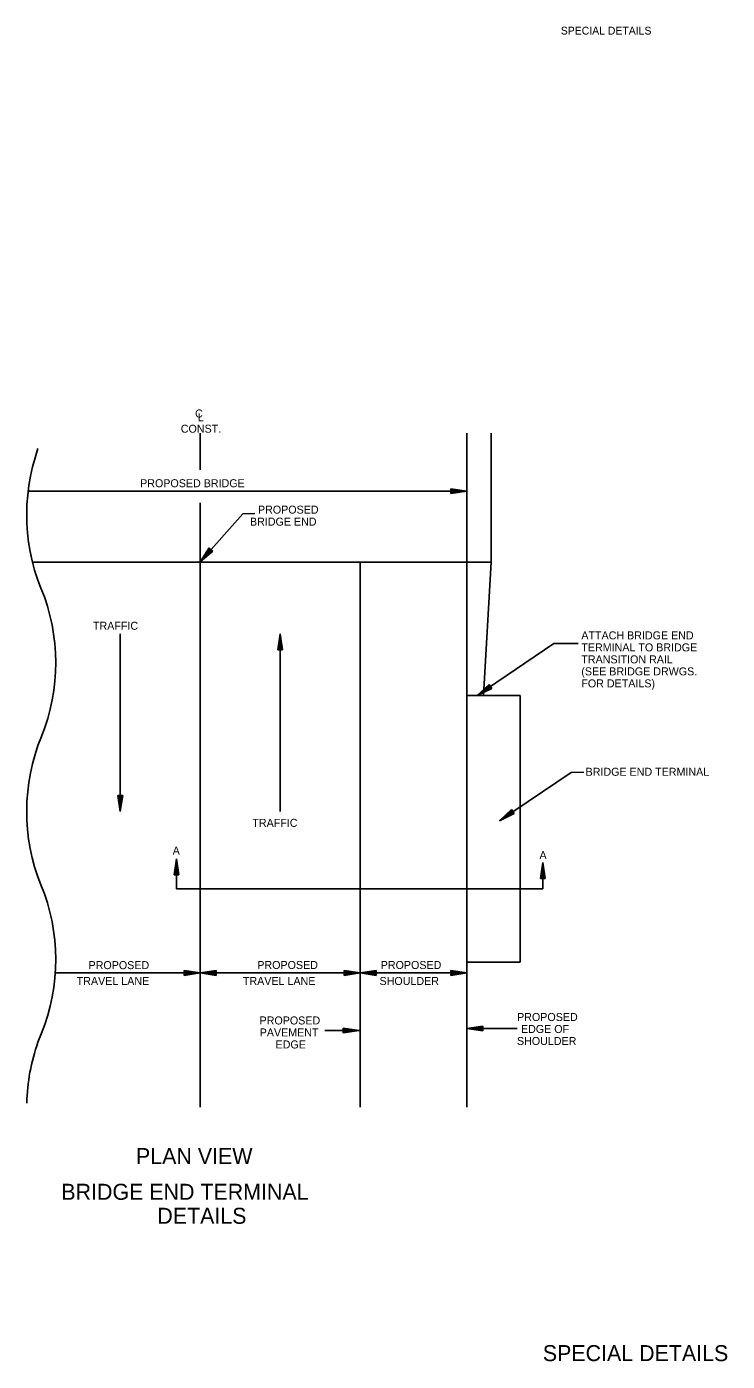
# Model space of a CAD drawing. Extents: x 1929624 to 1935547, y 596315 to 605721.
# Drawn here: x 1933758 to 1934284, y 604034 to 605035 of the extents above; entities that cross this region are included whole.
import ezdxf

# ---------------------------------------------------------------- set-up
doc = ezdxf.new("R2010")
doc.units = 0
for name, color, linetype in [('Default', 7, 'Continuous'), ('R_Annotation', 7, 'Continuous'), ('R_Border', 7, 'Continuous')]:
    doc.layers.add(name, color=color, linetype=linetype)

msp = doc.modelspace()

# ---------------------------------------------------------------- linework, layer by layer
at = {"layer": 'Default'}
for p, q in [((1933888.7, 604730.6), (1933888.7, 604703)), ((1934088.7, 604730.6), (1934088.7, 604633.8)), ((1934107, 604730.6), (1934107, 604633.8)), ((1933759.5, 604687), (1934088.7, 604687)), ((1934076.7, 604688.8), (1934088.7, 604687)), ((1934076.7, 604688.8), (1934076.7, 604685.2)), ((1934076.7, 604688.5), (1934086.7, 604687)), ((1934076.7, 604688.2), (1934084.6, 604687)), ((1934076.7, 604687.9), (1934082.6, 604687)), ((1934076.7, 604687.6), (1934080.6, 604687)), ((1934076.7, 604687.3), (1934078.6, 604687)), ((1934076.7, 604685.2), (1934088.7, 604687)), ((1934076.7, 604686.4), (1934080.6, 604687)), ((1934076.7, 604685.8), (1934084.6, 604687)), ((1934076.7, 604685.5), (1934086.7, 604687)), ((1934076.7, 604686.1), (1934082.6, 604687)), ((1934076.7, 604686.7), (1934078.6, 604687)), ((1933888.7, 604678.4), (1933888.7, 604225)), ((1933888.8, 604634.4), (1933920.7, 604670.1)), ((1933920.7, 604670.1), (1933929.7, 604670.2)), ((1933895.4, 604644.5), (1933888.8, 604634.4)), ((1933898.1, 604642.1), (1933888.8, 604634.4)), ((1933895.7, 604644.3), (1933890.1, 604635.9)), ((1933897.9, 604642.3), (1933890.1, 604635.9)), ((1933895.9, 604644.1), (1933891.5, 604637.4)), ((1933897.7, 604642.5), (1933891.5, 604637.4)), ((1933896.1, 604643.9), (1933892.8, 604638.9)), ((1933897.5, 604642.7), (1933892.8, 604638.9)), ((1933896.3, 604643.7), (1933894.2, 604640.4)), ((1933897.2, 604642.9), (1933894.2, 604640.4)), ((1933898.1, 604642.1), (1933895.4, 604644.5)), ((1933896.6, 604643.5), (1933895.5, 604641.9)), ((1933897, 604643.1), (1933895.5, 604641.9)), ((1933762.8, 604633.8), (1934107, 604633.8)), ((1934008.7, 604633.8), (1934008.7, 604225)), ((1934088.7, 604633.8), (1934088.7, 604533.8)), ((1934101.2, 604533.8), (1934107, 604633.8)), ((1933828.7, 604580), (1933828.7, 604446.9)), ((1933946.9, 604568), (1933948.7, 604580)), ((1933947.2, 604568), (1933948.7, 604578)), ((1933947.5, 604568), (1933948.7, 604575.9)), ((1933948.7, 604580), (1933948.7, 604446.9)), ((1933950.5, 604568), (1933948.7, 604580)), ((1933950.2, 604568), (1933948.7, 604578)), ((1933949.9, 604568), (1933948.7, 604575.9)), ((1933946.9, 604568), (1933950.5, 604568)), ((1933947.8, 604568), (1933948.7, 604573.9)), ((1933948.1, 604568), (1933948.7, 604571.9)), ((1933948.4, 604568), (1933948.7, 604569.9)), ((1933949.6, 604568), (1933948.7, 604573.9)), ((1933949.3, 604568), (1933948.7, 604571.9)), ((1933949, 604568), (1933948.7, 604569.9)), ((1934096.5, 604533.9), (1934154, 604572.9)), ((1934154, 604572.9), (1934172.1, 604572.9)), ((1934088.7, 604536), (1934088.7, 604225)), ((1934105.4, 604542.1), (1934096.5, 604533.9)), ((1934107.4, 604539.1), (1934096.5, 604533.9)), ((1934105.6, 604541.9), (1934098.2, 604535)), ((1934107.3, 604539.4), (1934098.2, 604535)), ((1934105.8, 604541.6), (1934099.9, 604536.2)), ((1934107.1, 604539.7), (1934099.9, 604536.2)), ((1934105.9, 604541.4), (1934101.5, 604537.3)), ((1934106.9, 604539.9), (1934101.5, 604537.3)), ((1934106.1, 604541.1), (1934103.2, 604538.5)), ((1934106.8, 604540.2), (1934103.2, 604538.5)), ((1934106.3, 604540.9), (1934104.9, 604539.6)), ((1934106.6, 604540.4), (1934104.9, 604539.6)), ((1934107.4, 604539.1), (1934105.4, 604542.1)), ((1934088.7, 604533.8), (1934088.7, 604333.8)), ((1934088.7, 604533.8), (1934128.7, 604533.8)), ((1934128.7, 604533.8), (1934128.7, 604333.8)), ((1934113.3, 604439.9), (1934166.9, 604476.1)), ((1934166.9, 604476.1), (1934176.4, 604476.2)), ((1933826.9, 604458.9), (1933828.7, 604446.9)), ((1933830.5, 604458.9), (1933826.9, 604458.9)), ((1933827.2, 604458.9), (1933828.7, 604448.9)), ((1933827.5, 604458.9), (1933828.7, 604450.9)), ((1933827.8, 604458.9), (1933828.7, 604452.9)), ((1933828.1, 604458.9), (1933828.7, 604455)), ((1933828.4, 604458.9), (1933828.7, 604457)), ((1933830.5, 604458.9), (1933828.7, 604446.9)), ((1933829.3, 604458.9), (1933828.7, 604455)), ((1933829.9, 604458.9), (1933828.7, 604450.9)), ((1933830.2, 604458.9), (1933828.7, 604448.9)), ((1933829.6, 604458.9), (1933828.7, 604452.9)), ((1933829, 604458.9), (1933828.7, 604457)), ((1934122.3, 604448.2), (1934113.3, 604439.9)), ((1934124.3, 604445.2), (1934113.3, 604439.9)), ((1934122.4, 604447.9), (1934115, 604441.1)), ((1934124.1, 604445.4), (1934115, 604441.1)), ((1934122.6, 604447.6), (1934116.7, 604442.2)), ((1934123.9, 604445.7), (1934116.7, 604442.2)), ((1934122.8, 604447.4), (1934118.4, 604443.3)), ((1934123.8, 604445.9), (1934118.4, 604443.3)), ((1934123, 604447.1), (1934120, 604444.5)), ((1934123.6, 604446.2), (1934120, 604444.5)), ((1934123.1, 604446.9), (1934121.7, 604445.6)), ((1934123.4, 604446.4), (1934121.7, 604445.6)), ((1934124.3, 604445.2), (1934122.3, 604448.2)), ((1933869.1, 604399.2), (1933870.9, 604411.2)), ((1933869.4, 604399.2), (1933870.9, 604409.2)), ((1933869.7, 604399.2), (1933870.9, 604407.1)), ((1933870, 604399.2), (1933870.9, 604405.1)), ((1933870.9, 604388.9), (1933870.9, 604411.2)), ((1933872.7, 604399.2), (1933870.9, 604411.2)), ((1933872.4, 604399.2), (1933870.9, 604409.2)), ((1933872.1, 604399.2), (1933870.9, 604407.1)), ((1933871.8, 604399.2), (1933870.9, 604405.1)), ((1934143.9, 604396.6), (1934145.7, 604408.6)), ((1934144.2, 604396.6), (1934145.7, 604406.6)), ((1934145.7, 604388.9), (1934145.7, 604408.6)), ((1934147.5, 604396.6), (1934145.7, 604408.6)), ((1934147.2, 604396.6), (1934145.7, 604406.6)), ((1933869.1, 604399.2), (1933872.7, 604399.2)), ((1933870.3, 604399.2), (1933870.9, 604403.1)), ((1933870.6, 604399.2), (1933870.9, 604401.1)), ((1933871.5, 604399.2), (1933870.9, 604403.1)), ((1933871.2, 604399.2), (1933870.9, 604401.1)), ((1934143.9, 604396.6), (1934147.5, 604396.6)), ((1934144.6, 604396.6), (1934145.7, 604404.6)), ((1934144.9, 604396.6), (1934145.7, 604402.6)), ((1934145.2, 604396.6), (1934145.7, 604400.5)), ((1934145.5, 604396.6), (1934145.7, 604398.5)), ((1934146.9, 604396.6), (1934145.7, 604404.6)), ((1934146.6, 604396.6), (1934145.7, 604402.6)), ((1934146.3, 604396.6), (1934145.7, 604400.5)), ((1934146, 604396.6), (1934145.7, 604398.5)), ((1933870.9, 604388.9), (1934145.7, 604388.9)), ((1933780.1, 604325.7), (1933888.7, 604325.7)), ((1933876.7, 604327.5), (1933888.7, 604325.7)), ((1933876.7, 604327.5), (1933876.7, 604323.9)), ((1933876.7, 604327.2), (1933886.7, 604325.7)), ((1933876.7, 604326.9), (1933884.6, 604325.7)), ((1933876.7, 604326.6), (1933882.6, 604325.7)), ((1933876.7, 604326.3), (1933880.6, 604325.7)), ((1933876.7, 604326), (1933878.6, 604325.7)), ((1933876.7, 604323.9), (1933888.7, 604325.7)), ((1933876.7, 604325.1), (1933880.6, 604325.7)), ((1933876.7, 604324.5), (1933884.6, 604325.7)), ((1933876.7, 604324.2), (1933886.7, 604325.7)), ((1933876.7, 604324.8), (1933882.6, 604325.7)), ((1933876.7, 604325.4), (1933878.6, 604325.7)), ((1933900.7, 604327.5), (1933888.7, 604325.7)), ((1933900.7, 604323.9), (1933888.7, 604325.7)), ((1933888.7, 604325.7), (1934008.7, 604325.7)), ((1933900.7, 604327.2), (1933890.7, 604325.7)), ((1933900.7, 604324.2), (1933890.7, 604325.7)), ((1933900.7, 604326.9), (1933892.8, 604325.7)), ((1933900.7, 604324.5), (1933892.8, 604325.7)), ((1933900.7, 604326.6), (1933894.8, 604325.7)), ((1933900.7, 604324.8), (1933894.8, 604325.7)), ((1933900.7, 604326.3), (1933896.8, 604325.7)), ((1933900.7, 604325.1), (1933896.8, 604325.7)), ((1933900.7, 604326), (1933898.8, 604325.7)), ((1933900.7, 604325.4), (1933898.8, 604325.7)), ((1933900.7, 604323.9), (1933900.7, 604327.5)), ((1933996.7, 604327.5), (1934008.7, 604325.7)), ((1933996.7, 604327.5), (1933996.7, 604323.9)), ((1933996.7, 604327.2), (1934006.7, 604325.7)), ((1933996.7, 604326.9), (1934004.6, 604325.7)), ((1933996.7, 604326.6), (1934002.6, 604325.7)), ((1933996.7, 604326.3), (1934000.6, 604325.7)), ((1933996.7, 604326), (1933998.6, 604325.7)), ((1933996.7, 604323.9), (1934008.7, 604325.7)), ((1933996.7, 604325.1), (1934000.6, 604325.7)), ((1933996.7, 604324.5), (1934004.6, 604325.7)), ((1933996.7, 604324.2), (1934006.7, 604325.7)), ((1933996.7, 604324.8), (1934002.6, 604325.7)), ((1933996.7, 604325.4), (1933998.6, 604325.7)), ((1934020.7, 604327.5), (1934008.7, 604325.7)), ((1934008.7, 604325.7), (1934088.7, 604325.7)), ((1934020.7, 604323.9), (1934008.7, 604325.7)), ((1934020.7, 604327.2), (1934010.7, 604325.7)), ((1934020.7, 604324.2), (1934010.7, 604325.7)), ((1934020.7, 604326.9), (1934012.8, 604325.7)), ((1934020.7, 604324.5), (1934012.8, 604325.7)), ((1934020.7, 604326.6), (1934014.8, 604325.7)), ((1934020.7, 604324.8), (1934014.8, 604325.7)), ((1934020.7, 604326.3), (1934016.8, 604325.7)), ((1934020.7, 604325.1), (1934016.8, 604325.7)), ((1934020.7, 604326), (1934018.8, 604325.7)), ((1934020.7, 604325.4), (1934018.8, 604325.7)), ((1934020.7, 604323.9), (1934020.7, 604327.5)), ((1934076.7, 604327.5), (1934088.7, 604325.7)), ((1934076.7, 604327.5), (1934076.7, 604323.9)), ((1934076.7, 604327.2), (1934086.7, 604325.7)), ((1934076.7, 604326.9), (1934084.6, 604325.7)), ((1934076.7, 604326.6), (1934082.6, 604325.7)), ((1934076.7, 604326.3), (1934080.6, 604325.7)), ((1934076.7, 604326), (1934078.6, 604325.7)), ((1934076.7, 604323.9), (1934088.7, 604325.7)), ((1934076.7, 604325.1), (1934080.6, 604325.7)), ((1934076.7, 604324.5), (1934084.6, 604325.7)), ((1934076.7, 604324.2), (1934086.7, 604325.7)), ((1934076.7, 604324.8), (1934082.6, 604325.7)), ((1934076.7, 604325.4), (1934078.6, 604325.7)), ((1934088.7, 604333.8), (1934128.7, 604333.8)), ((1934100.7, 604285.9), (1934088.7, 604284.1)), ((1934100.7, 604285.6), (1934090.7, 604284.1)), ((1934100.7, 604285.3), (1934092.8, 604284.1)), ((1934100.7, 604285), (1934094.8, 604284.1)), ((1934100.7, 604284.7), (1934096.8, 604284.1)), ((1934100.7, 604282.3), (1934100.7, 604285.9)), ((1933982.1, 604282.6), (1934008, 604282.6)), ((1933996, 604284.4), (1934008, 604282.6)), ((1933996, 604284.4), (1933996, 604280.8)), ((1933996, 604284.1), (1934006, 604282.6)), ((1933996, 604283.7), (1934003.9, 604282.6)), ((1933996, 604283.4), (1934001.9, 604282.6)), ((1933996, 604283.1), (1933999.9, 604282.6)), ((1933996, 604282.8), (1933997.9, 604282.6)), ((1933996, 604280.8), (1934008, 604282.6)), ((1933996, 604282), (1933999.9, 604282.6)), ((1933996, 604281.4), (1934003.9, 604282.6)), ((1933996, 604281.1), (1934006, 604282.6)), ((1933996, 604281.7), (1934001.9, 604282.6)), ((1933996, 604282.3), (1933997.9, 604282.6)), ((1934126.5, 604284.1), (1934088.7, 604284.1)), ((1934100.7, 604282.3), (1934088.7, 604284.1)), ((1934100.7, 604282.6), (1934090.7, 604284.1)), ((1934100.7, 604283), (1934092.8, 604284.1)), ((1934100.7, 604283.3), (1934094.8, 604284.1)), ((1934100.7, 604283.6), (1934096.8, 604284.1)), ((1934100.7, 604284.4), (1934098.8, 604284.1)), ((1934100.7, 604283.9), (1934098.8, 604284.1))]:
    msp.add_line(p, q, dxfattribs=at)
for centre, start, end in [((1933907.3, 604669.5), 160.5746, 204.5291), ((1933631.5, 604558.2), 335.4709, 19.4254), ((1933907.3, 604446.9), 160.5746, 204.5291), ((1933631.5, 604335.6), 335.4709, 19.4254), ((1933907.3, 604224.3), 160.5746, 178.5567)]:
    msp.add_arc(centre, 148.8, start, end, dxfattribs=at)

# ---------------------------------------------------------------- texts
for s, height, p in [('C', 6, (1933884.8, 604742.3)), ('L', 6, (1933886.9, 604739.5)), ('CONST.', 6, (1933874.1, 604730.9)), ('PROPOSED BRIDGE', 6, (1933843.6, 604690)), ('PROPOSED', 6, (1933932, 604670.2)), ('BRIDGE END', 6, (1933926, 604661.2)), ('TRAFFIC', 6, (1933808.2, 604583.1)), ('ATTACH BRIDGE END', 6, (1934174.6, 604575.9)), ('TERMINAL TO BRIDGE', 6, (1934174.6, 604566.9)), ('TRANSITION RAIL', 6, (1934174.6, 604557.9)), ('(SEE BRIDGE DRWGS.', 6, (1934174.6, 604548.9)), ('FOR DETAILS)', 6, (1934174.6, 604539.9)), ('BRIDGE END TERMINAL', 6, (1934177.8, 604473.6)), ('TRAFFIC', 6, (1933927.8, 604435.3)), ('A', 6, (1933868, 604414.5)), ('A', 6, (1934143.2, 604411.1)), ('PROPOSED', 6, (1933804.9, 604328.6)), ('PROPOSED', 6, (1933931.5, 604328.7)), ('PROPOSED', 6, (1934024.1, 604328.7)), ('TRAVEL LANE', 6, (1933796, 604316.7)), ('TRAVEL LANE', 6, (1933920.7, 604316.7)), ('SHOULDER', 6, (1934023.2, 604316.7)), ('PROPOSED', 6, (1934126.4, 604289.7)), ('PROPOSED', 6, (1933933.2, 604287.1)), ('EDGE OF', 6, (1934129.3, 604280.7)), ('PAVEMENT', 6, (1933933.3, 604278.1)), ('EDGE', 6, (1933945.2, 604269.1)), ('SHOULDER', 6, (1934126.3, 604271.7)), ('PLAN VIEW', 12, (1933840.5, 604182.4)), ('BRIDGE END TERMINAL', 12, (1933784.5, 604155.6)), ('DETAILS', 12, (1933856.5, 604137.6))]:
    msp.add_text(s, height=height, rotation=360, dxfattribs=at).set_placement(p)
at = {"layer": 'R_Annotation'}
msp.add_text('SPECIAL DETAILS', height=12, rotation=360, dxfattribs=at).set_placement((1934145.7, 604034.6))
at = {"layer": 'R_Border'}
msp.add_text('SPECIAL DETAILS', height=5.862, rotation=360, dxfattribs=at).set_placement((1934159.2, 605029.5))

doc.saveas('drawing.dxf')
